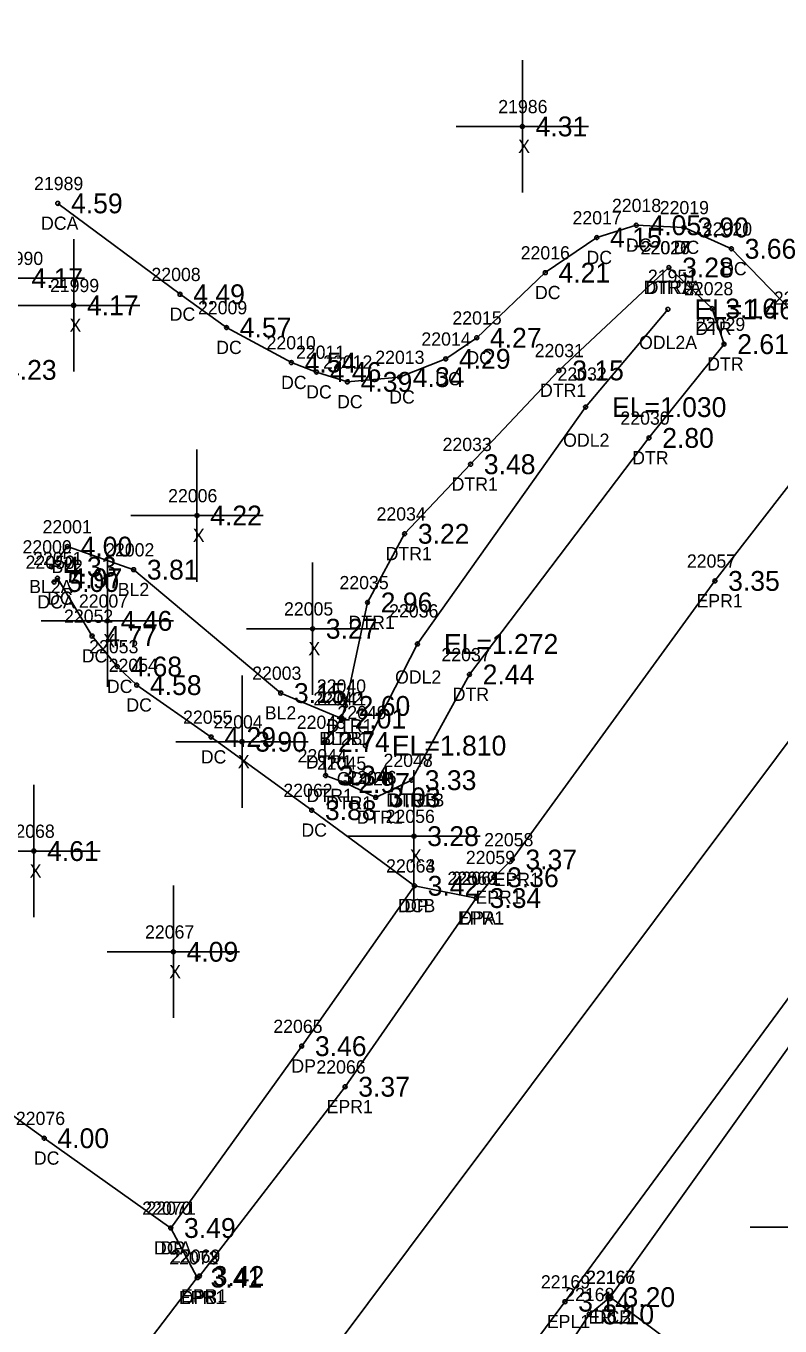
# Model space of a CAD drawing. Extents: x 2608745 to 2610333, y 641917 to 643463.
# Drawn here: x 2609958.6 to 2610015.6, y 641978.2 to 642076.5 of the extents above; entities that cross this region are included whole.
import ezdxf

# ---------------------------------------------------------------- set-up
doc = ezdxf.new("R2010")
doc.units = 0
for name, color, linetype in [('RD_DTM_BkLn1', 7, 'Continuous'), ('RD_DTM_BkLn_txCode', 7, 'Continuous'), ('RD_EX_Conc', 7, 'Continuous'), ('RD_EX_Conc_txCode', 7, 'Continuous'), ('RD_EX_Driveway', 7, 'Continuous'), ('RD_EX_Driveway_txCode', 7, 'Continuous'), ('RD_EX_H2O', 7, 'Continuous'), ('RD_EX_H2O_txCode', 7, 'Continuous'), ('RD_EX_Misc', 7, 'Continuous'), ('RD_EX_Misc_txCode', 7, 'Continuous'), ('RD_EX_Road', 7, 'Continuous'), ('RD_EX_Road_txCode', 7, 'Continuous'), ('RD_EX_TX_Conc_ELEV', 7, 'Continuous'), ('RD_EX_TX_Driveway_ELEV', 7, 'Continuous'), ('RD_EX_TX_H2O_ELEV', 7, 'Continuous'), ('RD_EX_TX_Misc_ELEV', 7, 'Continuous'), ('RD_EX_TX_Road_ELEV', 7, 'Continuous'), ('RD_SMD_Locator', 7, 'Continuous')]:
    doc.layers.add(name, color=color, linetype=linetype)

msp = doc.modelspace()

# ---------------------------------------------------------------- linework, layer by layer
at = {"layer": 'RD_DTM_BkLn1'}
for points in [[(2610092.08, 642124.262), (2610033.919, 642046.064), (2609975.15, 641967.52)], [(2609960.548, 642035.646), (2609961.739, 642037.165), (2609966.751, 642035.42), (2609977.865, 642026.094), (2609982.447, 642024.16)]]:
    msp.add_lwpolyline(points, dxfattribs=at)
at = {"layer": 'RD_EX_Conc'}
for points in [[(2609961.016, 642063.114), (2609970.253, 642056.24), (2609973.77, 642053.725), (2609978.671, 642051.077), (2609980.569, 642050.362), (2609982.905, 642049.619), (2609986.846, 642049.978), (2609990.334, 642051.359), (2609992.677, 642052.953), (2609997.86, 642057.875), (2610001.755, 642060.528), (2610004.736, 642061.459), (2610008.347, 642061.293), (2610011.93, 642059.679), (2610016.967, 642054.45), (2610017.895, 642052.738)], [(2609960.739, 642034.485), (2609960.987, 642034.768), (2609963.606, 642030.403), (2609965.507, 642028.097), (2609966.979, 642026.692), (2609972.604, 642022.767), (2609980.207, 642017.235), (2609987.972, 642011.523)], [(2609969.557, 641985.649), (2609959.989, 641992.436), (2609951.566, 641998.518), (2609948.754, 642000.513), (2609946.984, 642001.655), (2609944.027, 642002.836), (2609938.684, 642003.981), (2609938.35, 642004.199), (2609938.692, 642004.745)], [(2610024.204, 641964.927), (2610015.571, 641971.166), (2610010.305, 641974.813), (2610002.773, 641980.423)]]:
    msp.add_lwpolyline(points, dxfattribs=at)
at = {"layer": 'RD_EX_Driveway'}
msp.add_lwpolyline([(2609992.649, 642010.593), (2609987.972, 642011.523), (2609979.449, 641999.397), (2609969.557, 641985.649), (2609971.56, 641981.898)], dxfattribs=at)
at = {"layer": 'RD_EX_H2O'}
for points in [[(2610007.204, 642058.263), (2609998.896, 642050.485), (2609992.217, 642043.39), (2609987.228, 642038.134), (2609984.424, 642032.942), (2609982.751, 642025.12), (2609982.447, 642024.16), (2609981.196, 642022.387), (2609981.259, 642019.853), (2609982.724, 642019.295), (2609985.043, 642018.208), (2609987.753, 642019.505)], [(2610007.204, 642058.263), (2610010.468, 642055.164), (2610011.37, 642052.471), (2610005.7, 642045.381), (2609992.131, 642027.498), (2609987.753, 642019.505)], [(2610007.129, 642055.102), (2610000.907, 642047.712), (2609988.201, 642029.806), (2609984.271, 642022.119)]]:
    msp.add_lwpolyline(points, dxfattribs=at)
at = {"layer": 'RD_EX_Misc'}
for p, q in [((2609996.127, 642063.93), (2609996.127, 642073.93)), ((2609991.127, 642068.93), (2610001.127, 642068.93)), ((2609962.219, 642050.404), (2609962.219, 642060.404)), ((2609953.029, 642057.455), (2609963.029, 642057.455)), ((2609957.219, 642055.404), (2609967.219, 642055.404)), ((2609971.536, 642034.513), (2609971.536, 642044.513)), ((2609966.536, 642039.513), (2609976.536, 642039.513)), ((2609964.768, 642026.551), (2609964.768, 642036.551)), ((2609980.273, 642025.955), (2609980.273, 642035.955)), ((2609959.768, 642031.551), (2609969.768, 642031.551)), ((2609975.273, 642030.955), (2609985.273, 642030.955)), ((2609974.94, 642017.413), (2609974.94, 642027.413)), ((2609969.94, 642022.413), (2609979.94, 642022.413)), ((2609987.936, 642010.273), (2609987.936, 642020.273)), ((2609959.207, 642009.147), (2609959.207, 642019.147)), ((2609982.936, 642015.273), (2609992.936, 642015.273)), ((2609954.207, 642014.147), (2609964.207, 642014.147)), ((2609969.75, 642001.532), (2609969.75, 642011.532)), ((2609964.75, 642006.532), (2609974.75, 642006.532)), ((2610013.336, 641985.722), (2610023.336, 641985.722))]:
    msp.add_line(p, q, dxfattribs=at)
at = {"layer": 'RD_EX_Road'}
for points in [[(2610073.957, 642143.053), (2610073.967, 642133.893), (2610072.62, 642129.267), (2610072.125, 642123.733), (2610071.192, 642117.593), (2610042.94, 642077.419), (2610042.982, 642077.082), (2610020.807, 642047.622), (2610010.682, 642034.572), (2609995.36, 642013.506), (2609993.975, 642012.164), (2609992.649, 642010.593), (2609982.727, 641996.329), (2609971.725, 641982.02), (2609971.56, 641981.898), (2609965.999, 641974.618)], [(2610116.512, 642103.007), (2610109.419, 642106.335), (2610102.937, 642107.104), (2610095.974, 642105.732), (2610091.028, 642103.088), (2610067.446, 642071.713), (2610058.11, 642059.075), (2610043.044, 642039.371), (2610035.942, 642029.795), (2610030.832, 642022.851), (2609999.348, 641980.077), (2609984.87, 641960.622)], [(2610032.589, 642022.148), (2610025.693, 642013.504), (2610020.985, 642006.523), (2610018.112, 642001.928), (2610002.773, 641980.423), (2610001.184, 641979.118), (2609987.485, 641958.197)]]:
    msp.add_lwpolyline(points, dxfattribs=at)
at = {"layer": 'RD_SMD_Locator'}
for centre in [(2609996.127, 642068.93), (2609961.016, 642063.114), (2610004.736, 642061.459), (2610001.755, 642060.528), (2610008.347, 642061.293), (2610011.93, 642059.679), (2609997.86, 642057.875), (2610007.204, 642058.263), (2610007.204, 642058.263), (2609970.253, 642056.24), (2609962.219, 642055.404), (2610007.129, 642055.102), (2610010.468, 642055.164), (2609973.77, 642053.725), (2609992.677, 642052.953), (2610011.37, 642052.471), (2609978.671, 642051.077), (2609990.334, 642051.359), (2609980.569, 642050.362), (2609982.905, 642049.619), (2609986.846, 642049.978), (2609998.896, 642050.485), (2610000.907, 642047.712), (2610005.7, 642045.381), (2609992.217, 642043.39), (2609971.536, 642039.513), (2609987.228, 642038.134), (2609961.739, 642037.165), (2609960.548, 642035.646), (2609966.751, 642035.42), (2609960.739, 642034.485), (2609960.987, 642034.768), (2610010.682, 642034.572), (2609984.424, 642032.942), (2609964.768, 642031.551), (2609980.273, 642030.955), (2609963.606, 642030.403), (2609988.201, 642029.806), (2609965.507, 642028.097), (2609992.131, 642027.498), (2609966.979, 642026.692), (2609977.865, 642026.094), (2609982.751, 642025.12), (2609982.447, 642024.16), (2609982.447, 642024.16), (2609972.604, 642022.767), (2609974.94, 642022.413), (2609981.196, 642022.387), (2609984.271, 642022.119), (2609981.259, 642019.853), (2609982.724, 642019.295), (2609987.753, 642019.505), (2609987.753, 642019.505), (2609985.043, 642018.208), (2609980.207, 642017.235), (2609987.936, 642015.273), (2609959.207, 642014.147), (2609995.36, 642013.506), (2609987.972, 642011.523), (2609987.972, 642011.523), (2609993.975, 642012.164), (2609992.649, 642010.593), (2609992.649, 642010.593), (2609969.75, 642006.532), (2609979.449, 641999.397), (2609982.727, 641996.329), (2609959.989, 641992.436), (2609969.557, 641985.649), (2609969.557, 641985.649), (2609971.56, 641981.898), (2609971.56, 641981.898), (2609971.725, 641982.02), (2609999.348, 641980.077), (2610002.773, 641980.423), (2610002.773, 641980.423), (2610001.184, 641979.118)]:
    msp.add_circle(centre, 0.15, dxfattribs=at)

# ---------------------------------------------------------------- texts
at = {"layer": 'RD_DTM_BkLn_txCode'}
for s, p in [('22001', (2609959.864, 642038.165)), ('22000', (2609958.351, 642036.646)), ('22002', (2609964.594, 642036.42)), ('BL2', (2609960.534, 642035.165)), ('BL2A', (2609958.855, 642033.646)), ('BL2', (2609965.546, 642033.42)), ('22003', (2609975.707, 642027.094)), ('22041', (2609980.612, 642025.16)), ('BL2', (2609976.66, 642024.094)), ('BL2B', (2609980.769, 642022.16))]:
    msp.add_text(s, height=1, dxfattribs=at).set_placement(p)
at = {"layer": 'RD_EX_Conc_txCode'}
for s, p in [('21989', (2609959.221, 642064.114)), ('22018', (2610002.901, 642062.459)), ('22017', (2609999.921, 642061.528)), ('22019', (2610006.513, 642062.293)), ('DCA', (2609959.749, 642061.114)), ('22020', (2610009.772, 642060.679)), ('22016', (2609996.002, 642058.875)), ('DC', (2610000.976, 642058.528)), ('DC', (2610003.957, 642059.459)), ('DC', (2610007.568, 642059.293)), ('DC', (2610011.15, 642057.679)), ('22008', (2609968.095, 642057.24)), ('DC', (2609997.081, 642055.875)), ('22009', (2609971.613, 642054.725)), ('22021', (2610015.132, 642055.45)), ('DC', (2609969.473, 642054.24)), ('22015', (2609990.843, 642053.953)), ('DC', (2609972.99, 642051.725)), ('22010', (2609976.796, 642052.077)), ('22014', (2609988.499, 642052.359)), ('22011', (2609979.017, 642051.362)), ('22013', (2609985.012, 642050.978)), ('DC', (2609991.898, 642050.953)), ('22012', (2609981.07, 642050.619)), ('DC', (2609977.891, 642049.077)), ('DC', (2609989.554, 642049.359)), ('DC', (2609979.789, 642048.362)), ('DC', (2609986.067, 642047.978)), ('DC', (2609982.125, 642047.619)), ('22050', (2609958.582, 642035.485)), ('22051', (2609959.152, 642035.768)), ('DCA', (2609959.472, 642032.485)), ('DC', (2609960.207, 642032.768)), ('22052', (2609961.488, 642031.403)), ('22053', (2609963.389, 642029.097)), ('DC', (2609962.826, 642028.403)), ('22054', (2609964.861, 642027.692)), ('DC', (2609964.728, 642026.097)), ('DC', (2609966.2, 642024.692)), ('22055', (2609970.486, 642023.767)), ('DC', (2609971.824, 642020.767)), ('22062', (2609978.065, 642018.235)), ('DC', (2609979.427, 642015.235)), ('22063', (2609985.83, 642012.523)), ('DCB', (2609986.72, 642009.523)), ('22076', (2609957.848, 641993.436)), ('DC', (2609959.21, 641990.436)), ('22070', (2609967.399, 641986.649)), ('DCA', (2609968.289, 641983.649)), ('22166', (2610000.93, 641981.423)), ('DCB', (2610001.521, 641978.423))]:
    msp.add_text(s, height=1, dxfattribs=at).set_placement(p)
at = {"layer": 'RD_EX_Driveway_txCode'}
for s, p in [('22064', (2609985.83, 642012.523)), ('22061', (2609990.791, 642011.593)), ('DP', (2609987.192, 642009.523)), ('DPA', (2609991.381, 642008.593)), ('22065', (2609977.307, 642000.397)), ('DP', (2609978.669, 641997.397)), ('22071', (2609967.722, 641986.649)), ('DP', (2609968.777, 641983.649)), ('22072', (2609969.442, 641982.898)), ('DPB', (2609970.308, 641979.898))]:
    msp.add_text(s, height=1, dxfattribs=at).set_placement(p)
at = {"layer": 'RD_EX_H2O_txCode'}
for s, p in [('22026', (2610005.062, 642059.263)), ('22027', (2610005.086, 642059.263)), ('21951', (2610005.617, 642057.102)), ('DTR1A', (2610005.282, 642056.263)), ('DTRA', (2610005.448, 642056.263)), ('22028', (2610008.35, 642056.164)), ('DTR', (2610009.2, 642053.164)), ('22029', (2610009.252, 642053.471)), ('ODL2A', (2610004.948, 642052.102)), ('22031', (2609997.061, 642051.485)), ('22032', (2609998.789, 642049.712)), ('DTR', (2610010.102, 642050.471)), ('DTR1', (2609997.463, 642048.485)), ('22030', (2610003.542, 642046.381)), ('22033', (2609990.099, 642044.39)), ('ODL2', (2609999.214, 642044.712)), ('DTR', (2610004.432, 642043.381)), ('DTR1', (2609990.784, 642041.39)), ('22034', (2609985.109, 642039.134)), ('DTR1', (2609985.794, 642036.134)), ('22035', (2609982.306, 642033.942)), ('22036', (2609986.059, 642031.806)), ('DTR1', (2609982.991, 642030.942)), ('22037', (2609990.012, 642028.498)), ('22040', (2609980.594, 642026.12)), ('ODL2', (2609986.508, 642026.806)), ('22042', (2609980.328, 642025.16)), ('DTR', (2609990.863, 642025.498)), ('22043', (2609979.078, 642023.387)), ('22049', (2609982.153, 642024.119)), ('DTR1', (2609981.318, 642023.12)), ('DTR1', (2609981.014, 642022.16)), ('22044', (2609979.141, 642020.853)), ('DTR1', (2609979.763, 642020.387)), ('22045', (2609980.606, 642020.295)), ('22047', (2609985.635, 642020.505)), ('22048', (2609985.635, 642020.505)), ('22046', (2609982.901, 642019.208)), ('ODL2B', (2609982.106, 642019.119)), ('DTR1', (2609979.826, 642017.853)), ('DTR1', (2609981.291, 642017.295)), ('DTR1B', (2609985.848, 642017.505)), ('DTRB', (2609986.013, 642017.505)), ('DTR1', (2609983.61, 642016.208))]:
    msp.add_text(s, height=1, dxfattribs=at).set_placement(p)
at = {"layer": 'RD_EX_Misc_txCode'}
for s, p in [('21986', (2609994.308, 642069.93)), ('X', (2609995.812, 642066.93)), ('21990', (2609956.194, 642058.455)), ('21999', (2609960.423, 642056.404)), ('X', (2609961.904, 642053.404)), ('22006', (2609969.355, 642040.513)), ('X', (2609971.221, 642037.513)), ('22007', (2609962.611, 642032.551)), ('22005', (2609978.116, 642031.955)), ('X', (2609964.453, 642029.551)), ('X', (2609979.958, 642028.955)), ('22004', (2609972.782, 642023.413)), ('X', (2609974.625, 642020.413)), ('22056', (2609985.794, 642016.273)), ('22068', (2609957.066, 642015.147)), ('X', (2609987.621, 642013.273)), ('X', (2609958.892, 642012.147)), ('22067', (2609967.609, 642007.532)), ('X', (2609969.435, 642004.532))]:
    msp.add_text(s, height=1, dxfattribs=at).set_placement(p)
at = {"layer": 'RD_EX_Road_txCode'}
for s, p in [('22057', (2610008.564, 642035.572)), ('EPR1', (2610009.289, 642032.572)), ('22058', (2609993.242, 642014.506)), ('22059', (2609991.857, 642013.164)), ('22060', (2609990.468, 642011.593)), ('EPR1', (2609993.967, 642011.506)), ('EPR1', (2609992.581, 642010.164)), ('EPR1', (2609991.255, 642008.593)), ('22066', (2609980.562, 641997.329)), ('EPR1', (2609981.333, 641994.329)), ('22073', (2609969.442, 641982.898)), ('22069', (2609969.583, 641983.02)), ('22169', (2609997.529, 641981.077)), ('22167', (2610000.954, 641981.423)), ('EPR1', (2609970.331, 641980.02)), ('22168', (2609999.365, 641980.118)), ('EPR1', (2609970.166, 641979.898)), ('EPL1', (2609997.978, 641978.077)), ('EPL2', (2610001.119, 641978.423))]:
    msp.add_text(s, height=1, dxfattribs=at).set_placement(p)
at = {"layer": 'RD_EX_TX_Conc_ELEV'}
for s, p in [('4.59', (2609962.016, 642062.364)), ('4.05', (2610005.736, 642060.709)), ('3.90', (2610009.347, 642060.543)), ('4.15', (2610002.755, 642059.778)), ('3.66', (2610012.93, 642058.929)), ('4.21', (2609998.86, 642057.125)), ('4.49', (2609971.253, 642055.49)), ('4.57', (2609974.77, 642052.975)), ('4.27', (2609993.677, 642052.203)), ('4.54', (2609979.671, 642050.327)), ('4.29', (2609991.334, 642050.609)), ('4.46', (2609981.569, 642049.612)), ('4.34', (2609987.846, 642049.228)), ('4.39', (2609983.905, 642048.869)), ('5.00', (2609961.739, 642033.735)), ('4.97', (2609961.987, 642034.018)), ('4.77', (2609964.606, 642029.653)), ('4.68', (2609966.507, 642027.347)), ('4.58', (2609967.979, 642025.942)), ('4.29', (2609973.604, 642022.017)), ('3.88', (2609981.207, 642016.485)), ('3.42', (2609988.972, 642010.773)), ('4.00', (2609960.989, 641991.686)), ('3.49', (2609970.557, 641984.899)), ('3.20', (2610003.773, 641979.673))]:
    msp.add_text(s, height=1.5, dxfattribs=at).set_placement(p)
at = {"layer": 'RD_EX_TX_Driveway_ELEV'}
for s, p in [('3.42', (2609988.972, 642010.773)), ('3.34', (2609993.649, 642009.843)), ('3.46', (2609980.449, 641998.647)), ('3.49', (2609970.557, 641984.899)), ('3.41', (2609972.56, 641981.148))]:
    msp.add_text(s, height=1.5, dxfattribs=at).set_placement(p)
at = {"layer": 'RD_EX_TX_H2O_ELEV'}
for s, p in [('3.28', (2610008.204, 642057.513)), ('3.28', (2610008.204, 642057.513)), ('EL=1.466', (2610009.129, 642054.352)), ('3.16', (2610011.468, 642054.414)), ('2.61', (2610012.37, 642051.721)), ('3.15', (2609999.896, 642049.735)), ('EL=1.030', (2610002.907, 642046.962)), ('2.80', (2610006.7, 642044.631)), ('3.48', (2609993.217, 642042.64)), ('3.22', (2609988.228, 642037.384)), ('2.96', (2609985.424, 642032.192)), ('EL=1.272', (2609990.201, 642029.056)), ('2.44', (2609993.131, 642026.748)), ('2.60', (2609983.751, 642024.37)), ('2.01', (2609983.447, 642023.41)), ('2.74', (2609982.196, 642021.637)), ('EL=1.810', (2609986.271, 642021.369)), ('3.34', (2609982.259, 642019.103)), ('3.33', (2609988.753, 642018.755)), ('3.33', (2609988.753, 642018.755)), ('2.97', (2609983.724, 642018.545)), ('3.03', (2609986.043, 642017.458))]:
    msp.add_text(s, height=1.5, dxfattribs=at).set_placement(p)
at = {"layer": 'RD_EX_TX_Misc_ELEV'}
for s, p in [('4.31', (2609997.127, 642068.18)), ('4.17', (2609959.029, 642056.705)), ('4.17', (2609963.219, 642054.654)), ('4.23', (2609957.024, 642049.774)), ('4.22', (2609972.536, 642038.763)), ('4.00', (2609962.739, 642036.415)), ('4.33', (2609961.548, 642034.896)), ('3.81', (2609967.751, 642034.67)), ('4.46', (2609965.768, 642030.801)), ('3.27', (2609981.273, 642030.205)), ('3.15', (2609978.865, 642025.344)), ('2.01', (2609983.447, 642023.41)), ('3.90', (2609975.94, 642021.663)), ('3.28', (2609988.936, 642014.523)), ('4.61', (2609960.207, 642013.397)), ('4.09', (2609970.75, 642005.782))]:
    msp.add_text(s, height=1.5, dxfattribs=at).set_placement(p)
at = {"layer": 'RD_EX_TX_Road_ELEV'}
for s, p in [('3.35', (2610011.682, 642033.822)), ('3.37', (2609996.36, 642012.756)), ('3.36', (2609994.975, 642011.414)), ('3.34', (2609993.649, 642009.843)), ('3.37', (2609983.727, 641995.579)), ('3.41', (2609972.56, 641981.148)), ('3.42', (2609972.725, 641981.27)), ('3.20', (2610003.773, 641979.673)), ('3.14', (2610000.348, 641979.327)), ('3.10', (2610002.184, 641978.368))]:
    msp.add_text(s, height=1.5, dxfattribs=at).set_placement(p)

doc.saveas('drawing.dxf')
